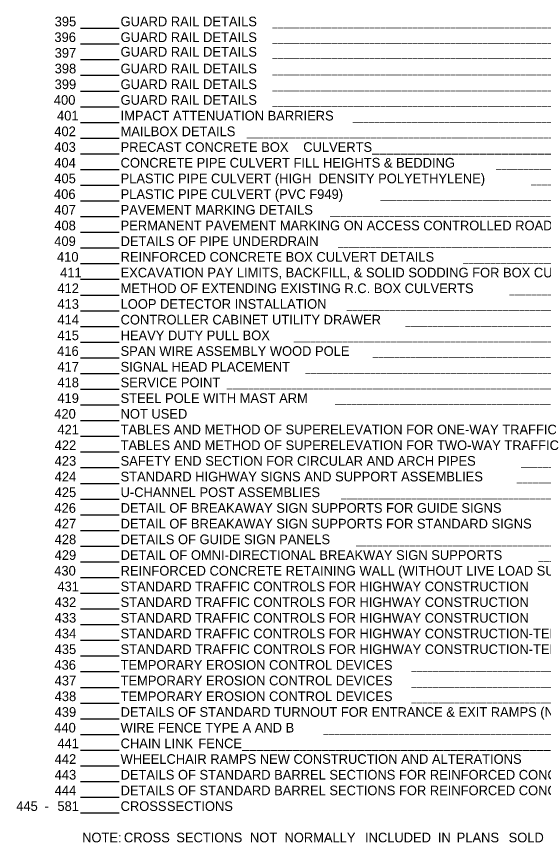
# Model space of a CAD drawing. Extents: x 1224738 to 1230974, y 151304 to 152345.
# Drawn here: x 1227316 to 1227596.7, y 151438.5 to 151878.5 of the extents above; entities that cross this region are included whole.
import ezdxf

# ---------------------------------------------------------------- set-up
doc = ezdxf.new("R2010")
doc.units = 0
doc.layers.add('R_Dimension', color=7, linetype='Continuous')

msp = doc.modelspace()

# ---------------------------------------------------------------- linework, layer by layer
at = {"layer": 'R_Dimension'}
for p, q in [((1227350.11, 151872.25), (1227370.59, 151872.25)), ((1227350.11, 151863.89), (1227370.59, 151863.89)), ((1227350.11, 151855.53), (1227370.59, 151855.53)), ((1227350.11, 151847.17), (1227370.59, 151847.17)), ((1227350.11, 151838.81), (1227370.59, 151838.81)), ((1227350.11, 151830.45), (1227370.59, 151830.45)), ((1227350.11, 151822.09), (1227370.59, 151822.09)), ((1227350.11, 151813.73), (1227370.59, 151813.73)), ((1227350.11, 151805.37), (1227370.59, 151805.37)), ((1227350.11, 151797.01), (1227370.59, 151797.01)), ((1227350.11, 151788.65), (1227370.59, 151788.65)), ((1227350.11, 151780.3), (1227370.59, 151780.3)), ((1227350.11, 151771.94), (1227370.59, 151771.94)), ((1227350.11, 151763.58), (1227370.59, 151763.58)), ((1227350.11, 151755.22), (1227370.59, 151755.22)), ((1227350.11, 151746.86), (1227370.59, 151746.86)), ((1227350.11, 151738.5), (1227370.59, 151738.5)), ((1227350.11, 151730.14), (1227370.59, 151730.14)), ((1227350.11, 151721.78), (1227370.59, 151721.78)), ((1227350.11, 151713.42), (1227370.59, 151713.42)), ((1227350.11, 151705.06), (1227370.59, 151705.06)), ((1227350.11, 151696.7), (1227370.59, 151696.7)), ((1227350.11, 151688.34), (1227370.59, 151688.34)), ((1227350.11, 151679.98), (1227370.59, 151679.98)), ((1227350.11, 151671.62), (1227370.59, 151671.62)), ((1227350.11, 151663.26), (1227370.59, 151663.26)), ((1227350.11, 151654.9), (1227370.59, 151654.9)), ((1227350.11, 151646.54), (1227370.59, 151646.54)), ((1227350.11, 151638.19), (1227370.59, 151638.19)), ((1227350.11, 151629.83), (1227370.59, 151629.83)), ((1227350.11, 151621.47), (1227370.59, 151621.47)), ((1227350.11, 151613.11), (1227370.59, 151613.11)), ((1227350.11, 151604.75), (1227370.59, 151604.75)), ((1227350.11, 151596.39), (1227370.59, 151596.39)), ((1227350.11, 151588.03), (1227370.59, 151588.03)), ((1227350.11, 151579.67), (1227370.59, 151579.67)), ((1227350.11, 151571.31), (1227370.59, 151571.31)), ((1227350.11, 151562.95), (1227370.59, 151562.95)), ((1227350.11, 151554.59), (1227370.59, 151554.59)), ((1227350.11, 151546.23), (1227370.59, 151546.23)), ((1227350.11, 151537.87), (1227370.59, 151537.87)), ((1227350.11, 151529.51), (1227370.59, 151529.51)), ((1227350.11, 151521.15), (1227370.59, 151521.15)), ((1227350.11, 151512.79), (1227370.59, 151512.79)), ((1227350.11, 151504.43), (1227370.59, 151504.43)), ((1227350.11, 151496.08), (1227370.59, 151496.08)), ((1227350.11, 151487.72), (1227370.59, 151487.72)), ((1227350.11, 151479.36), (1227370.59, 151479.36)), ((1227350.11, 151471), (1227370.59, 151471)), ((1227350.11, 151462.64), (1227370.59, 151462.64)), ((1227350.11, 151454.28), (1227370.59, 151454.28))]:
    msp.add_line(p, q, dxfattribs=at)

# ---------------------------------------------------------------- texts
for s, height, p in [('395', 5.144, (1227336.3, 151873.28)), ('GUARD RAIL DETAILS', 5.1443, (1227371.42, 151873.28)), ('396', 5.144, (1227336.16, 151864.92)), ('GUARD RAIL DETAILS', 5.1443, (1227371.42, 151864.92)), ('_________________________________________________________________________________________________________________________________________', 3.85819, (1227452.35, 151873.28)), ('397', 5.144, (1227336.3, 151856.56)), ('GUARD RAIL DETAILS', 5.1443, (1227371.42, 151857.14)), ('_________________________________________________________________________________________________________________________________________', 3.85819, (1227452.35, 151864.92)), ('__________________________________________________________________________________________________________________________________________', 3.85819, (1227452.35, 151857.14)), ('398', 5.144, (1227336.3, 151848.2)), ('GUARD RAIL DETAILS', 5.1443, (1227371.42, 151848.2)), ('__________________________________________________________________________________________________________________________________________', 3.85819, (1227452.35, 151848.2)), ('399', 5.144, (1227336.28, 151839.84)), ('GUARD RAIL DETAILS', 5.1443, (1227371.42, 151839.84)), ('_________________________________________________________________________________________________________________________________________', 3.85819, (1227452.35, 151839.84)), ('400', 5.144, (1227335.87, 151831.48)), ('GUARD RAIL DETAILS', 5.1443, (1227371.42, 151831.48)), ('_________________________________________________________________________________________________________________________________________', 3.85819, (1227452.35, 151831.48)), ('401', 5.144, (1227337.55, 151823.12)), ('IMPACT ATTENUATION BARRIERS', 5.1443, (1227371.42, 151823.12)), ('____________________________________________________________________________________________________________________________', 3.85819, (1227495.05, 151823.12)), ('402', 5.144, (1227336.1, 151814.76)), ('MAILBOX DETAILS', 5.1443, (1227371.42, 151814.76)), ('_____________________________________________________________________________________________________________________________________________', 3.85819, (1227438.74, 151814.76)), ('403', 5.144, (1227336.1, 151806.4)), ('PRECAST CONCRETE BOX', 5.1443, (1227371.42, 151806.4)), (' CULVERTS_________________________________________________________________________________________', 5.1443, (1227466.81, 151806.4)), ('404', 5.144, (1227336.1, 151798.04)), ('CONCRETE PIPE CULVERT FILL HEIGHTS & BEDDING', 5.1443, (1227371.42, 151798.04)), ('405', 5.144, (1227336.1, 151789.68)), ('PLASTIC PIPE CULVERT (HIGH  DENSITY POLYETHYLENE)', 5.1443, (1227371.42, 151789.68)), ('____________________________________________________________________________________________________', 3.8582, (1227571.52, 151798.04)), ('406', 5.144, (1227335.95, 151781.32)), ('PLASTIC PIPE CULVERT (PVC F949)', 5.1443, (1227371.42, 151781.32)), ('______________________________________________________________________________________________', 3.8582, (1227590.07, 151789.68)), ('407', 5.144, (1227336.1, 151772.96)), ('PAVEMENT MARKING DETAILS', 5.1443, (1227371.42, 151772.97)), ('_______________________________________________________________________________________________________________________', 3.85819, (1227509.95, 151781.32)), ('408', 5.144, (1227336.1, 151764.61)), ('PERMANENT PAVEMENT MARKING ON ACCESS CONTROLLED ROADWAYS', 5.1443, (1227371.42, 151764.61)), ('________________________________________________________________________________________________________________________________', 3.85819, (1227482.98, 151772.97)), ('409', 5.144, (1227336.08, 151756.25)), ('DETAILS OF PIPE UNDERDRAIN', 5.1443, (1227371.42, 151756.25)), ('______________________________________________________________________________________________________________________________', 3.85819, (1227487.35, 151756.25)), ('410', 5.144, (1227337.53, 151747.89)), ('REINFORCED CONCRETE BOX CULVERT DETAILS', 5.1443, (1227371.42, 151747.89)), ('_________________________________________________________________________________________________________', 3.85819, (1227553.94, 151747.89)), ('411', 5.144, (1227339.22, 151739.53)), ('EXCAVATION PAY LIMITS, BACKFILL, & SOLID SODDING FOR BOX CULVERTS', 5.1443, (1227371.42, 151739.53)), ('412', 5.144, (1227337.76, 151731.17)), ('METHOD OF EXTENDING EXISTING R.C. BOX CULVERTS', 5.1443, (1227371.42, 151731.17)), ('__________________________________________________________________________________________________', 3.8582, (1227578.65, 151731.17)), ('413', 5.144, (1227337.76, 151722.81)), ('LOOP DETECTOR INSTALLATION', 5.1443, (1227371.42, 151722.81)), ('414', 5.144, (1227337.76, 151714.45)), ('CONTROLLER CABINET UTILITY DRAWER', 5.1443, (1227371.42, 151714.45)), ('_____________________________________________________________________________________________________________________________', 3.85819, (1227491.89, 151722.81)), ('415', 5.144, (1227337.76, 151706.09)), ('HEAVY DUTY PULL BOX', 5.1443, (1227371.42, 151706.09)), ('___________________________________________________________________________________________________________________', 3.85819, (1227523.24, 151714.45)), ('416', 5.144, (1227337.62, 151697.73)), ('SPAN WIRE ASSEMBLY WOOD POLE', 5.1443, (1227371.42, 151697.73)), ('_____________________________________________________________________________________________________________________________________', 3.85819, (1227463.78, 151706.09)), ('417', 5.144, (1227337.76, 151689.37)), ('SIGNAL HEAD PLACEMENT', 5.1443, (1227371.42, 151689.37)), ('________________________________________________________________________________________________________________________', 3.85819, (1227505.82, 151697.73)), ('418', 5.144, (1227337.76, 151681.01)), ('SERVICE POINT', 5.1443, (1227371.42, 151681.01)), ('___________________________________________________________________________________________________________________________________', 3.85819, (1227469.93, 151689.37)), ('_________________________________________________________________________________________________________________________________________________', 3.85819, (1227428.05, 151681.01)), ('419', 5.144, (1227337.74, 151672.65)), ('STEEL POLE WITH MAST ARM', 5.1443, (1227371.42, 151672.65)), ('_______________________________________________________________________________________________________________________________', 3.85819, (1227485.81, 151672.65)), ('420', 5.144, (1227336.08, 151664.29)), ('NOT USED', 5.144, (1227371.42, 151664.29)), ('421', 5.144, (1227337.76, 151655.93)), ('TABLES AND METHOD OF SUPERELEVATION FOR ONE-WAY TRAFFIC', 5.1443, (1227371.42, 151655.93)), ('422', 5.144, (1227336.3, 151647.57)), ('TABLES AND METHOD OF SUPERELEVATION FOR TWO-WAY TRAFFIC', 5.1443, (1227371.42, 151647.57)), ('423', 5.144, (1227336.3, 151639.21)), ('SAFETY END SECTION FOR CIRCULAR AND ARCH PIPES', 5.1443, (1227371.42, 151639.21)), ('424', 5.144, (1227336.3, 151630.85)), ('STANDARD HIGHWAY SIGNS AND SUPPORT ASSEMBLIES', 5.1443, (1227371.42, 151630.86)), ('_______________________________________________________________________________________________', 3.8582, (1227584.89, 151639.21)), ('425', 5.144, (1227336.3, 151622.5)), ('U-CHANNEL POST ASSEMBLIES', 5.1443, (1227371.42, 151622.5)), ('________________________________________________________________________________________________', 3.8582, (1227582.46, 151630.86)), ('426', 5.144, (1227336.16, 151614.14)), ('DETAIL OF BREAKAWAY SIGN SUPPORTS FOR GUIDE SIGNS', 5.1443, (1227371.42, 151614.14)), ('______________________________________________________________________________________________________________________________', 3.85819, (1227488.97, 151622.5)), ('427', 5.144, (1227336.3, 151605.78)), ('DETAIL OF BREAKAWAY SIGN SUPPORTS FOR STANDARD SIGNS', 5.1443, (1227371.42, 151605.78)), ('428', 5.144, (1227336.3, 151597.42)), ('DETAILS OF GUIDE SIGN PANELS', 5.1443, (1227371.42, 151597.42)), ('___________________________________________________________________________________________________________________________', 3.85819, (1227496.83, 151597.42)), ('429', 5.144, (1227336.28, 151589.06)), ('DETAIL OF OMNI-DIRECTIONAL BREAKWAY SIGN SUPPORTS', 5.1443, (1227371.42, 151589.06)), ('____________________________________________________________________________________________', 3.8582, (1227594.04, 151589.06)), ('430', 5.144, (1227336.08, 151580.7)), ('REINFORCED CONCRETE RETAINING WALL (WITHOUT LIVE LOAD SURCHARGE)______________________________________________________', 5.14425, (1227371.42, 151580.7)), ('431', 5.144, (1227337.76, 151572.34)), ('STANDARD TRAFFIC CONTROLS FOR HIGHWAY CONSTRUCTION', 5.1443, (1227371.42, 151572.34)), ('432', 5.144, (1227336.3, 151563.98)), ('STANDARD TRAFFIC CONTROLS FOR HIGHWAY CONSTRUCTION', 5.1443, (1227371.42, 151563.98)), ('433', 5.144, (1227336.3, 151555.62)), ('STANDARD TRAFFIC CONTROLS FOR HIGHWAY CONSTRUCTION', 5.1443, (1227371.42, 151555.62)), ('434', 5.144, (1227336.3, 151547.26)), ('STANDARD TRAFFIC CONTROLS FOR HIGHWAY CONSTRUCTION-TEMPORARY PRECAST BARRIER', 5.1443, (1227371.42, 151547.26)), ('435', 5.144, (1227336.3, 151538.9)), ('STANDARD TRAFFIC CONTROLS FOR HIGHWAY CONSTRUCTION-TEMPORARY PRECAST BARRIER', 5.1443, (1227371.42, 151538.9)), ('436', 5.144, (1227336.16, 151530.54)), ('TEMPORARY EROSION CONTROL DEVICES', 5.1443, (1227371.42, 151530.54)), ('437', 5.144, (1227336.3, 151522.18)), ('TEMPORARY EROSION CONTROL DEVICES', 5.1443, (1227371.42, 151522.18)), ('___________________________________________________________________________________________________________________', 3.85819, (1227526.32, 151530.54)), ('438', 5.144, (1227336.3, 151513.82)), ('TEMPORARY EROSION CONTROL DEVICES', 5.1443, (1227371.42, 151513.82)), ('___________________________________________________________________________________________________________________', 3.85819, (1227526.32, 151522.18)), ('__________________________________________________________________________________________________________________', 3.85819, (1227526.32, 151513.82)), ('439', 5.144, (1227336.28, 151505.46)), ('DETAILS OF STANDARD TURNOUT FOR ENTRANCE & EXIT RAMPS (NON-REINFORCED)', 5.1443, (1227371.42, 151505.46)), ('440', 5.144, (1227336.08, 151497.1)), ('WIRE FENCE TYPE A AND B', 5.1443, (1227371.42, 151497.1)), ('_________________________________________________________________________________________________________________________________', 3.85819, (1227479.49, 151497.1)), ('441', 5.144, (1227337.76, 151488.74)), ('CHAIN LINK', 5.144, (1227371.42, 151488.75)), (' FENCE__________________________________________________________________________________________________________', 5.14425, (1227410.9, 151488.75)), ('442', 5.144, (1227336.3, 151480.39)), ('WHEELCHAIR RAMPS NEW CONSTRUCTION AND ALTERATIONS', 5.1443, (1227371.42, 151480.39)), ('443', 5.144, (1227336.3, 151472.03)), ('DETAILS OF STANDARD BARREL SECTIONS FOR REINFORCED CONCRETE BOX CULVERTS', 5.1443, (1227371.42, 151472.03)), ('444', 5.144, (1227336.3, 151463.67)), ('DETAILS OF STANDARD BARREL SECTIONS FOR REINFORCED CONCRETE BOX CULVERTS', 5.1443, (1227371.42, 151463.67)), ('445', 5.144, (1227315.82, 151455.31)), ('581', 5.144, (1227337.76, 151455.31)), ('CROSS', 5.144, (1227371.42, 151455.31)), (' SECTIONS', 5.144, (1227394.19, 151455.31)), ('-', 5.14, (1227330.88, 151455.31)), ('NOTE:', 5.144, (1227350.94, 151438.59)), (' CROSS', 5.144, (1227371.28, 151438.59)), (' SECTIONS', 5.144, (1227399.19, 151438.59)), (' NOT', 5.144, (1227438.44, 151438.59)), (' NORMALLY', 5.144, (1227456.83, 151438.59)), (' INCLUDED', 5.144, (1227499.72, 151438.59)), (' IN', 5.144, (1227538.53, 151438.59)), (' PLANS', 5.144, (1227548.57, 151438.59)), (' SOLD', 5.144, (1227576.24, 151438.59))]:
    msp.add_text(s, height=height, dxfattribs=at).set_placement(p)

doc.saveas('drawing.dxf')
